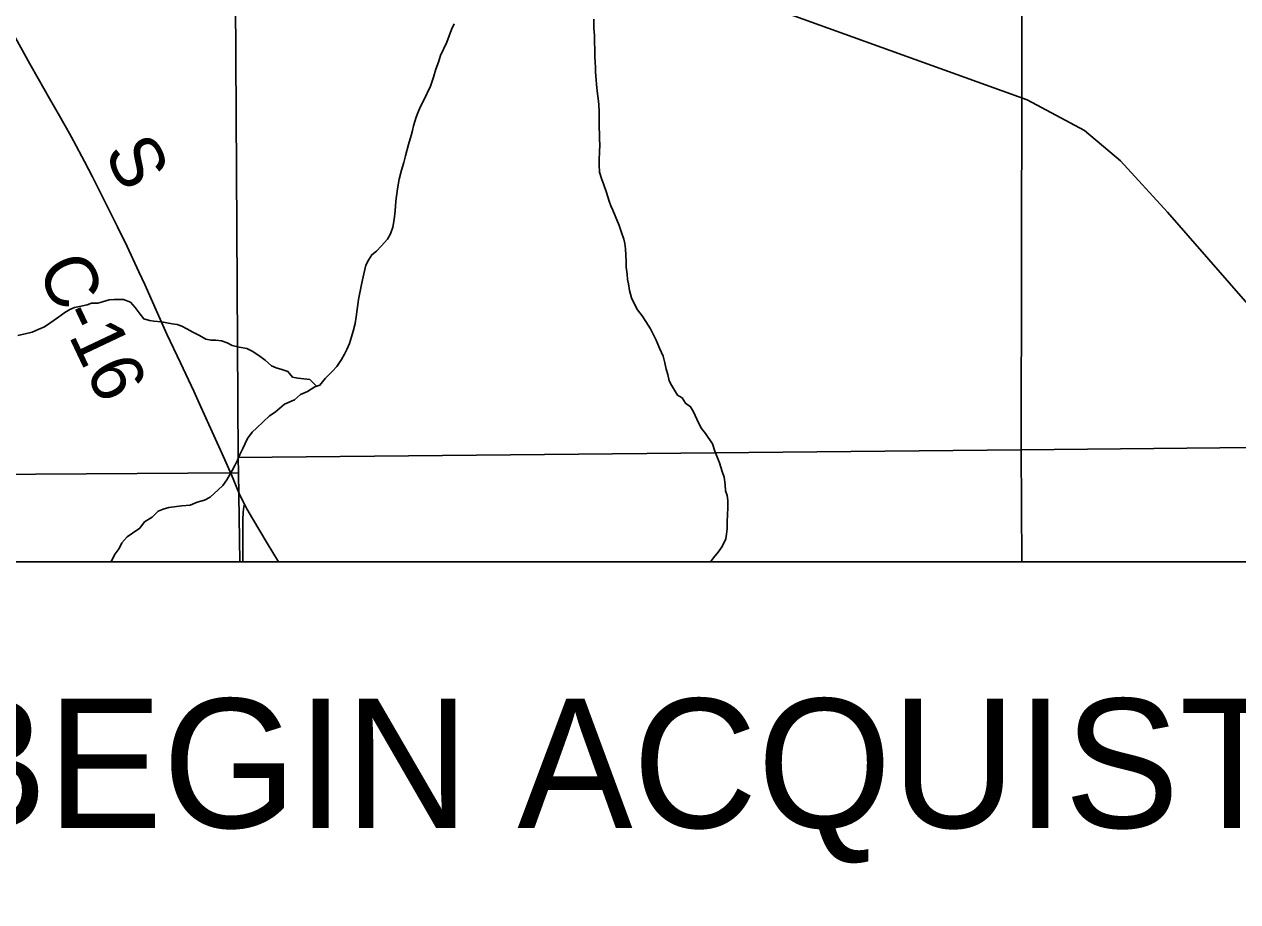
# Model space of a CAD drawing. Extents: x 0 to 34, y 0 to 22.
# Drawn here: x 3.385 to 4.701, y 18.929 to 19.88 of the extents above; entities that cross this region are included whole.
import ezdxf

# ---------------------------------------------------------------- set-up
doc = ezdxf.new("R2010")
doc.units = 0
for name, color, linetype in [('GM_X_County_Road', 7, 'Continuous'), ('GM_X_County_Road_Text', 7, 'Continuous'), ('GM_X_Minor_River', 7, 'Continuous'), ('GM_X_Rail_Line', 7, 'Continuous'), ('GM_X_Section', 7, 'Continuous'), ('SH_Text', 7, 'Continuous')]:
    doc.layers.add(name, color=color, linetype=linetype)

msp = doc.modelspace()

# ---------------------------------------------------------------- linework, layer by layer
at = {"layer": 'GM_X_County_Road'}
for points in [[(3.624, 19.3601), (3.6223, 19.3633), (3.6185, 19.3717), (3.6101, 19.3917), (3.6001, 19.4145), (3.591, 19.4346), (3.5769, 19.4655), (3.5691, 19.4824), (3.5547, 19.5133), (3.5401, 19.5444), (3.53, 19.5672), (3.516, 19.5981), (3.5095, 19.612), (3.4968, 19.6394), (3.4864, 19.6608), (3.475, 19.6839), (3.4594, 19.7148), (3.4506, 19.7317), (3.4387, 19.7538), (3.4343, 19.762), (3.4235, 19.7809), (3.4129, 19.7998), (3.4006, 19.8214), (3.3915, 19.8376), (3.372, 19.8729)], [(3.6223, 19.2976), (3.6224, 19.3121), (3.6224, 19.3432), (3.6227, 19.3514), (3.6235, 19.3572), (3.624, 19.3601)], [(3.661, 19.2976), (3.6489, 19.3178), (3.6328, 19.3444), (3.6266, 19.3551), (3.624, 19.3601)]]:
    msp.add_lwpolyline(points, dxfattribs=at)
at = {"layer": 'GM_X_Minor_River'}
for points in [[(3.8515, 19.8807), (3.8485, 19.8746), (3.8462, 19.8678), (3.8436, 19.8609), (3.8367, 19.8465), (3.8345, 19.8393), (3.8318, 19.8317), (3.8292, 19.8229), (3.8258, 19.8134), (3.8182, 19.7974), (3.8147, 19.7906), (3.8121, 19.7845), (3.8102, 19.7796), (3.8075, 19.7701), (3.8064, 19.7651), (3.8049, 19.7598), (3.8019, 19.7499), (3.7988, 19.7378), (3.7969, 19.7305), (3.7943, 19.7222), (3.792, 19.7123), (3.7901, 19.702), (3.7883, 19.6887), (3.7875, 19.6781), (3.7864, 19.6686), (3.7849, 19.6602), (3.7823, 19.6533), (3.7792, 19.6473), (3.7724, 19.6397), (3.7674, 19.6343), (3.7621, 19.6305), (3.7587, 19.6245), (3.7556, 19.6191), (3.7534, 19.6096), (3.7522, 19.6032), (3.7507, 19.5963), (3.7477, 19.5819), (3.7462, 19.5712), (3.7454, 19.5632), (3.7443, 19.556), (3.7421, 19.5476), (3.7402, 19.5416), (3.7379, 19.5343), (3.7352, 19.5279), (3.7326, 19.5226), (3.7295, 19.5169), (3.7242, 19.5093), (3.7196, 19.5043), (3.7116, 19.4963), (3.7059, 19.4891), (3.7006, 19.4872), (3.6926, 19.4823), (3.685, 19.4789), (3.6785, 19.4732), (3.6674, 19.4686), (3.6575, 19.4599), (3.6511, 19.4557), (3.6377, 19.4427), (3.6324, 19.4382), (3.6275, 19.4313), (3.6225, 19.4203), (3.6191, 19.4139), (3.6165, 19.4078), (3.6138, 19.4021), (3.6108, 19.3964), (3.6051, 19.3865), (3.6005, 19.3804), (3.5955, 19.3755), (3.5868, 19.3675), (3.5807, 19.3644), (3.5727, 19.3622), (3.5654, 19.3591)], [(4.003, 19.886), (4.0031, 19.8761), (4.0035, 19.8681), (4.0035, 19.8609), (4.0039, 19.8529), (4.0039, 19.8453), (4.0043, 19.8392), (4.0047, 19.8335), (4.0047, 19.8285), (4.0055, 19.8202), (4.0059, 19.8152), (4.007, 19.805), (4.0078, 19.8), (4.0082, 19.7935), (4.0086, 19.7852), (4.0087, 19.7681), (4.0091, 19.762), (4.0091, 19.7559), (4.0095, 19.7498), (4.0091, 19.7422), (4.0087, 19.7335), (4.0088, 19.7281), (4.0092, 19.7201), (4.0111, 19.7133), (4.0138, 19.7061), (4.0165, 19.6981), (4.0195, 19.6886), (4.0215, 19.6836), (4.0234, 19.6787), (4.0261, 19.6726), (4.0303, 19.662), (4.033, 19.6547), (4.0353, 19.6475), (4.0364, 19.6426), (4.0372, 19.6369), (4.038, 19.6232), (4.038, 19.6171), (4.0392, 19.6095), (4.0396, 19.6038), (4.0404, 19.5988), (4.0415, 19.5916), (4.0438, 19.5836), (4.0477, 19.5756), (4.0504, 19.5707), (4.0553, 19.5642), (4.0595, 19.5581), (4.0645, 19.5501), (4.0707, 19.538), (4.0741, 19.5292), (4.078, 19.5205), (4.0799, 19.5132), (4.0814, 19.5064), (4.083, 19.5007), (4.0845, 19.4939), (4.0872, 19.4889), (4.0937, 19.4783), (4.0987, 19.4752), (4.1025, 19.4695), (4.1078, 19.4657), (4.1109, 19.46), (4.1163, 19.4482), (4.1197, 19.4421), (4.1239, 19.4368), (4.1316, 19.4254), (4.1343, 19.4174), (4.137, 19.4102), (4.1393, 19.4048), (4.142, 19.3953), (4.1443, 19.3892), (4.1455, 19.3813), (4.1458, 19.3744), (4.1474, 19.3695), (4.1482, 19.3641), (4.1482, 19.3569), (4.1478, 19.3482), (4.1475, 19.3417), (4.1475, 19.3333), (4.1467, 19.3276), (4.146, 19.3223), (4.1422, 19.3143), (4.1376, 19.3079), (4.1327, 19.3018), (4.1293, 19.2976)], [(3.7023, 19.4878), (3.6949, 19.4952), (3.6819, 19.4967), (3.6761, 19.4979), (3.6712, 19.504), (3.6647, 19.5059), (3.6586, 19.5078), (3.6536, 19.5101), (3.6467, 19.5161), (3.6398, 19.5211), (3.6326, 19.526), (3.6268, 19.5287), (3.6184, 19.5302), (3.6108, 19.5321), (3.6055, 19.5348), (3.5993, 19.5371), (3.5932, 19.5378), (3.5879, 19.5378), (3.5822, 19.539), (3.5753, 19.5428), (3.568, 19.5466), (3.5615, 19.55), (3.5562, 19.5531), (3.5512, 19.555), (3.5459, 19.5557), (3.5401, 19.5565), (3.534, 19.5576), (3.526, 19.5584), (3.5211, 19.5592), (3.515, 19.5611), (3.5111, 19.566), (3.5058, 19.5733), (3.5004, 19.579), (3.4928, 19.582), (3.4828, 19.582), (3.4775, 19.5816), (3.4703, 19.5794), (3.4653, 19.5778), (3.4584, 19.5778), (3.4535, 19.5763), (3.4451, 19.5744), (3.4397, 19.5733), (3.4348, 19.571), (3.4294, 19.568), (3.4214, 19.5619), (3.4131, 19.5562), (3.4074, 19.5524), (3.4005, 19.5494), (3.394, 19.5467), (3.3864, 19.5448), (3.3784, 19.5429)], [(3.5654, 19.3591), (3.5563, 19.3584), (3.5422, 19.3565), (3.5361, 19.3546), (3.5307, 19.3523), (3.5242, 19.3458), (3.5159, 19.3409), (3.5105, 19.3341), (3.5029, 19.3287), (3.4968, 19.3246), (3.4911, 19.3181), (3.4881, 19.312), (3.4839, 19.3063), (3.4801, 19.2987), (3.4794, 19.2976)]]:
    msp.add_lwpolyline(points, dxfattribs=at)
at = {"layer": 'GM_X_Rail_Line'}
msp.add_lwpolyline([(2.7155, 20.9), (2.73, 20.8809), (3.0413, 20.4799), (3.1308, 20.3674), (3.1683, 20.3431), (3.6096, 20.1154), (3.6962, 20.0743), (3.8747, 20.0142), (4.4727, 19.7986), (4.5351, 19.7653), (4.5741, 19.7323), (4.625, 19.6768), (4.956, 19.2976)], dxfattribs=at)
at = {"layer": 'GM_X_Section'}
for points in [[(4.4682, 20.4307), (5.4771, 20.4356), (5.472, 19.4291), (4.4662, 19.4189)], [(3.6121, 20.4224), (4.4682, 20.4307), (4.4662, 19.4189), (3.6173, 19.4106), (3.6114, 20.403)], [(3.6114, 20.403), (3.6173, 19.4106), (3.6177, 19.3939), (2.6269, 19.3875), (2.614, 20.3953)], [(4.4724, 18.5805), (4.4738, 18.4018), (5.4223, 18.414), (5.4724, 18.4134), (5.472, 19.4291), (4.4662, 19.4189), (4.4671, 19.2976), (5.3223, 19.2976), (5.3223, 18.5805)], [(4.4671, 19.2976), (4.4662, 19.4189), (3.6173, 19.4106), (3.6177, 19.3939), (3.619, 19.2976)], [(3.619, 19.2976), (3.6177, 19.3939), (2.6269, 19.3875), (2.6434, 18.3786), (3.6306, 18.3893), (3.6281, 18.5805), (3.1024, 18.5805), (3.1024, 19.2976)]]:
    msp.add_lwpolyline(points, close=True, dxfattribs=at)
at = {"layer": 'SH_Text'}
msp.add_lwpolyline([(3.1024, 19.2976), (5.3223, 19.2976), (5.3223, 18.5805), (3.1024, 18.5805)], close=True, dxfattribs=at)

# ---------------------------------------------------------------- texts
at = {"layer": 'GM_X_County_Road_Text'}
for s, height, rotation, p in [('S', 0.0568, 296.5662, (3.4713, 19.7417)), ('C-16', 0.05682, 295.3623, (3.3986, 19.6154))]:
    msp.add_text(s, height=height, rotation=rotation, dxfattribs=at).set_placement(p)
at = {"layer": 'SH_Text'}
msp.add_text('BEGIN ACQUISTION', height=0.14, dxfattribs=at).set_placement((3.2855, 19.0091))

doc.saveas('drawing.dxf')
